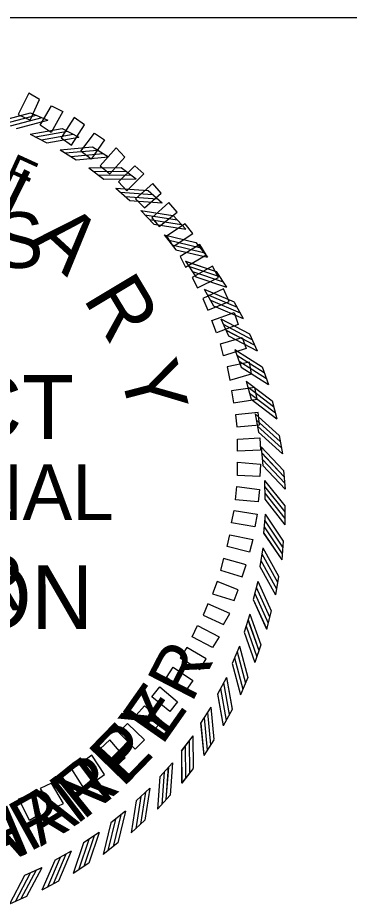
# Model space of a CAD drawing. Extents: x 16 to 1228740, y 11 to 152440.
# Drawn here: x 17.7977 to 17.8643, y 10.8205 to 10.9986 of the extents above; entities that cross this region are included whole.
import ezdxf

# ---------------------------------------------------------------- set-up
doc = ezdxf.new("R2010")
doc.units = 0
for name, color, linetype in [('R_No Plot', 7, 'Continuous'), ('STAMP_FRED', 7, 'Continuous'), ('STAMP_JUSTIN', 7, 'Continuous'), ('STAMP_PRELIM', 7, 'Continuous')]:
    doc.layers.add(name, color=color, linetype=linetype)

msp = doc.modelspace()

# ---------------------------------------------------------------- linework, layer by layer
at = {"layer": 'R_No Plot'}
msp.add_line((17.888, 10.99864), (17.47349, 10.99864), dxfattribs=at)
at = {"layer": 'STAMP_FRED'}
for p, q in [((17.80029, 10.97955), (17.80376, 10.97807)), ((17.80666, 10.9764), (17.80999, 10.97463)), ((17.80024, 10.97526), (17.80358, 10.97349)), ((17.80625, 10.97212), (17.80943, 10.97009)), ((17.81275, 10.97273), (17.81592, 10.9707)), ((17.81199, 10.9685), (17.81499, 10.96621)), ((17.81851, 10.96857), (17.82151, 10.96628)), ((17.8174, 10.96442), (17.82021, 10.96189)), ((17.82391, 10.96395), (17.82671, 10.96142)), ((17.82246, 10.95991), (17.82505, 10.95715)), ((17.82891, 10.9589), (17.83149, 10.95615)), ((17.82713, 10.95499), (17.82948, 10.95203)), ((17.83347, 10.95345), (17.83582, 10.9505)), ((17.83138, 10.9497), (17.83348, 10.94656)), ((17.83757, 10.94765), (17.83966, 10.94451)), ((17.83518, 10.94408), (17.83701, 10.94078)), ((17.84118, 10.94152), (17.843, 10.93822)), ((17.8385, 10.93817), (17.84005, 10.93472)), ((17.84427, 10.93512), (17.84581, 10.93169)), ((17.84132, 10.932), (17.84258, 10.92844)), ((17.84682, 10.92849), (17.84807, 10.92494)), ((17.84362, 10.92562), (17.84458, 10.92197)), ((17.84881, 10.92167), (17.84977, 10.91802)), ((17.84539, 10.91908), (17.84605, 10.91535)), ((17.85023, 10.91471), (17.85089, 10.91099)), ((17.84661, 10.9124), (17.84696, 10.90864)), ((17.85108, 10.90765), (17.85142, 10.9039)), ((17.84728, 10.90566), (17.84731, 10.90188)), ((17.84738, 10.89887), (17.8471, 10.89511)), ((17.85133, 10.90055), (17.85137, 10.89678)), ((17.84693, 10.89211), (17.84634, 10.88837)), ((17.851, 10.89345), (17.85073, 10.88969)), ((17.85009, 10.8864), (17.8495, 10.88268)), ((17.84591, 10.8854), (17.84502, 10.88173)), ((17.8486, 10.87945), (17.8477, 10.87579)), ((17.84435, 10.8788), (17.84316, 10.87522)), ((17.84225, 10.87235), (17.84076, 10.86888)), ((17.84653, 10.87265), (17.84534, 10.86908)), ((17.83962, 10.8661), (17.83786, 10.86276)), ((17.84392, 10.86605), (17.84243, 10.86258)), ((17.83649, 10.86009), (17.83445, 10.85691)), ((17.84076, 10.85968), (17.839, 10.85635)), ((17.83287, 10.85435), (17.83058, 10.85135)), ((17.83709, 10.85359), (17.83506, 10.85042)), ((17.82879, 10.84894), (17.82625, 10.84613)), ((17.83293, 10.84783), (17.83065, 10.84483)), ((17.82427, 10.84388), (17.82152, 10.84129)), ((17.82831, 10.84243), (17.82579, 10.83963)), ((17.81935, 10.83921), (17.81639, 10.83686)), ((17.82326, 10.83743), (17.82051, 10.83485)), ((17.81407, 10.83496), (17.81092, 10.83286)), ((17.81782, 10.83287), (17.81486, 10.83052)), ((17.80845, 10.83116), (17.80514, 10.82933)), ((17.80254, 10.82784), (17.79909, 10.82629)), ((17.81201, 10.82877), (17.80888, 10.82667)), ((17.80589, 10.82516), (17.80259, 10.82333)), ((17.79949, 10.82207), (17.79605, 10.82052))]:
    msp.add_line(p, q, dxfattribs=at)
for points in [[(17.79398, 10.97788), (17.80029, 10.97955)], [(17.79509, 10.9774), (17.8014, 10.97906)], [(17.79631, 10.97691), (17.80261, 10.97857)], [(17.79746, 10.9764), (17.80376, 10.97807)], [(17.80023, 10.97526), (17.80665, 10.9764)], [(17.8013, 10.97468), (17.80772, 10.97582)], [(17.80247, 10.97409), (17.80889, 10.97523)], [(17.80357, 10.97349), (17.81, 10.97463)], [(17.80625, 10.97212), (17.81274, 10.97273)], [(17.80726, 10.97146), (17.81376, 10.97206)], [(17.80838, 10.97078), (17.81487, 10.97138)], [(17.80943, 10.97009), (17.81593, 10.9707)], [(17.81198, 10.9685), (17.8185, 10.96857)], [(17.81294, 10.96776), (17.81946, 10.96782)], [(17.814, 10.96699), (17.82052, 10.96705)], [(17.81499, 10.96621), (17.82151, 10.96628)], [(17.8174, 10.96442), (17.8239, 10.96395)], [(17.81829, 10.9636), (17.8248, 10.96313)], [(17.81928, 10.96274), (17.82579, 10.96227)], [(17.8202, 10.96189), (17.82671, 10.96142)], [(17.82246, 10.95991), (17.8289, 10.9589)], [(17.82328, 10.95901), (17.82972, 10.95801)], [(17.8242, 10.95808), (17.83064, 10.95707)], [(17.82505, 10.95716), (17.83149, 10.95615)], [(17.82713, 10.95499), (17.83347, 10.95345)], [(17.82787, 10.95403), (17.83421, 10.9525)], [(17.82871, 10.95303), (17.83505, 10.95149)], [(17.82948, 10.95203), (17.83582, 10.9505)], [(17.83138, 10.9497), (17.83757, 10.94765)], [(17.83204, 10.94869), (17.83823, 10.94663)], [(17.83279, 10.94762), (17.83898, 10.94556)], [(17.83348, 10.94656), (17.83967, 10.94451)], [(17.83517, 10.94409), (17.84117, 10.94153)], [(17.83575, 10.94302), (17.84175, 10.94046)], [(17.83641, 10.94189), (17.84241, 10.93933)], [(17.83701, 10.94078), (17.84301, 10.93822)], [(17.83849, 10.93817), (17.84426, 10.93513)], [(17.83898, 10.93706), (17.84475, 10.93402)], [(17.83955, 10.93588), (17.84531, 10.93283)], [(17.84005, 10.93473), (17.84582, 10.93168)], [(17.84132, 10.93201), (17.84681, 10.92849)], [(17.84171, 10.93086), (17.84721, 10.92735)], [(17.84217, 10.92963), (17.84767, 10.92612)], [(17.84258, 10.92845), (17.84808, 10.92493)], [(17.84362, 10.92563), (17.84881, 10.92167)], [(17.84392, 10.92445), (17.8491, 10.9205)], [(17.84428, 10.92319), (17.84947, 10.91924)], [(17.84459, 10.92197), (17.84977, 10.91802)], [(17.84539, 10.91908), (17.85023, 10.91471)], [(17.84558, 10.91788), (17.85043, 10.91351)], [(17.84584, 10.9166), (17.85068, 10.91223)], [(17.84605, 10.91536), (17.85089, 10.91099)], [(17.84661, 10.91241), (17.85107, 10.90765)], [(17.84671, 10.9112), (17.85117, 10.90645)], [(17.84686, 10.9099), (17.85132, 10.90514)], [(17.84696, 10.90865), (17.85143, 10.90389)], [(17.84727, 10.90566), (17.85133, 10.90055)], [(17.84727, 10.90445), (17.85133, 10.89934)], [(17.84731, 10.90314), (17.85137, 10.89803)], [(17.84731, 10.90188), (17.85137, 10.89677)], [(17.84738, 10.89888), (17.851, 10.89345)], [(17.84728, 10.89767), (17.8509, 10.89225)], [(17.84721, 10.89636), (17.85083, 10.89094)], [(17.84711, 10.89511), (17.85073, 10.88969)], [(17.84692, 10.89211), (17.85009, 10.88641)], [(17.84672, 10.89092), (17.84989, 10.88521)], [(17.84634, 10.88838), (17.84951, 10.88267)], [(17.84655, 10.88962), (17.84971, 10.88391)], [(17.84591, 10.88541), (17.84859, 10.87946)], [(17.84533, 10.88295), (17.84801, 10.877)], [(17.84561, 10.88423), (17.8483, 10.87828)], [(17.84502, 10.88173), (17.84771, 10.87579)], [(17.84396, 10.87766), (17.84614, 10.87151)], [(17.84435, 10.87881), (17.84653, 10.87266)], [(17.84357, 10.87641), (17.84575, 10.87026)], [(17.84316, 10.87522), (17.84534, 10.86907)], [(17.84225, 10.87236), (17.84391, 10.86605)], [(17.84176, 10.87125), (17.84343, 10.86494)], [(17.84077, 10.86888), (17.84243, 10.86258)], [(17.84127, 10.87003), (17.84294, 10.86373)], [(17.83904, 10.86504), (17.84018, 10.85862)], [(17.83962, 10.86611), (17.84076, 10.85968)], [(17.83846, 10.86387), (17.8396, 10.85745)], [(17.83786, 10.86276), (17.839, 10.85634)], [(17.83649, 10.86009), (17.83709, 10.8536)], [(17.83514, 10.85796), (17.83575, 10.85146)], [(17.83582, 10.85908), (17.83643, 10.85258)], [(17.83446, 10.85691), (17.83506, 10.85041)], [(17.83287, 10.85436), (17.83293, 10.84784)], [(17.83212, 10.8534), (17.83219, 10.84688)], [(17.83058, 10.85135), (17.83065, 10.84483)], [(17.83135, 10.85234), (17.83142, 10.84582)], [(17.82797, 10.84805), (17.82749, 10.84154)], [(17.82879, 10.84894), (17.82831, 10.84244)], [(17.82626, 10.84613), (17.82579, 10.83963)], [(17.82711, 10.84706), (17.82664, 10.84055)], [(17.82427, 10.84388), (17.82326, 10.83744)], [(17.82244, 10.84214), (17.82144, 10.8357)], [(17.82338, 10.84306), (17.82237, 10.83661)], [(17.82152, 10.84129), (17.82051, 10.83485)], [(17.8184, 10.83847), (17.81686, 10.83213)], [(17.81936, 10.83921), (17.81782, 10.83287)], [(17.8164, 10.83686), (17.81486, 10.83052)], [(17.81739, 10.83763), (17.81585, 10.83129)], [(17.81407, 10.83496), (17.81202, 10.82877)], [(17.81198, 10.83355), (17.80993, 10.82736)], [(17.81305, 10.8343), (17.811, 10.82811)], [(17.81093, 10.83286), (17.80887, 10.82667)], [(17.80625, 10.82993), (17.80369, 10.82393)], [(17.80738, 10.83059), (17.80483, 10.82459)], [(17.80845, 10.83116), (17.80589, 10.82516)], [(17.80254, 10.82784), (17.79949, 10.82208)], [(17.80515, 10.82933), (17.80259, 10.82333)], [(17.79909, 10.82629), (17.79605, 10.82052)], [(17.80024, 10.82679), (17.7972, 10.82102)], [(17.80143, 10.82736), (17.79838, 10.82159)]]:
    msp.add_lwpolyline(points, dxfattribs=at)
at = {"layer": 'STAMP_JUSTIN'}
for p, q in [((17.80029, 10.97955), (17.80376, 10.97807)), ((17.80666, 10.9764), (17.80999, 10.97463)), ((17.80024, 10.97526), (17.80358, 10.97349)), ((17.80625, 10.97212), (17.80943, 10.97009)), ((17.81275, 10.97273), (17.81592, 10.97069)), ((17.81198, 10.9685), (17.81499, 10.96621)), ((17.81851, 10.96857), (17.8215, 10.96628)), ((17.8174, 10.96442), (17.8202, 10.96189)), ((17.82391, 10.96395), (17.8267, 10.96142)), ((17.82246, 10.95991), (17.82505, 10.95715)), ((17.82891, 10.9589), (17.83149, 10.95615)), ((17.82713, 10.95499), (17.82948, 10.95203)), ((17.83347, 10.95345), (17.83581, 10.9505)), ((17.83138, 10.9497), (17.83348, 10.94656)), ((17.83757, 10.94765), (17.83966, 10.94451)), ((17.83518, 10.94408), (17.83701, 10.94078)), ((17.84118, 10.94152), (17.843, 10.93822)), ((17.8385, 10.93817), (17.84005, 10.93472)), ((17.84427, 10.93512), (17.84581, 10.93169)), ((17.84132, 10.932), (17.84258, 10.92844)), ((17.84682, 10.92849), (17.84807, 10.92494)), ((17.84362, 10.92562), (17.84458, 10.92197)), ((17.84881, 10.92167), (17.84977, 10.91802)), ((17.84539, 10.91908), (17.84604, 10.91536)), ((17.85023, 10.91471), (17.85089, 10.91099)), ((17.84661, 10.91241), (17.84695, 10.90864)), ((17.85107, 10.90765), (17.85142, 10.9039)), ((17.84727, 10.90566), (17.84731, 10.90188)), ((17.84738, 10.89888), (17.8471, 10.89511)), ((17.85133, 10.90055), (17.85137, 10.89678)), ((17.84692, 10.89211), (17.84634, 10.88838)), ((17.851, 10.89345), (17.85073, 10.88969)), ((17.85009, 10.8864), (17.8495, 10.88268)), ((17.84591, 10.8854), (17.84502, 10.88173)), ((17.84859, 10.87946), (17.8477, 10.87579)), ((17.84435, 10.8788), (17.84316, 10.87522)), ((17.84225, 10.87236), (17.84076, 10.86888)), ((17.84653, 10.87265), (17.84534, 10.86908)), ((17.83962, 10.8661), (17.83785, 10.86276)), ((17.84391, 10.86605), (17.84243, 10.86258)), ((17.83649, 10.86009), (17.83445, 10.85691)), ((17.84076, 10.85968), (17.839, 10.85635)), ((17.83287, 10.85435), (17.83057, 10.85135)), ((17.83709, 10.85359), (17.83506, 10.85042)), ((17.82879, 10.84894), (17.82625, 10.84614)), ((17.83293, 10.84783), (17.83064, 10.84484)), ((17.82427, 10.84388), (17.82151, 10.84129)), ((17.82831, 10.84243), (17.82578, 10.83964)), ((17.81935, 10.83921), (17.81639, 10.83686)), ((17.82326, 10.83743), (17.82051, 10.83485)), ((17.81407, 10.83496), (17.81092, 10.83286)), ((17.81782, 10.83287), (17.81486, 10.83053)), ((17.80845, 10.83116), (17.80514, 10.82933)), ((17.80253, 10.82784), (17.79909, 10.82629)), ((17.81201, 10.82877), (17.80887, 10.82668)), ((17.80589, 10.82516), (17.80259, 10.82334)), ((17.79949, 10.82207), (17.79605, 10.82053))]:
    msp.add_line(p, q, dxfattribs=at)
for points in [[(17.79398, 10.97788), (17.80029, 10.97955)], [(17.79509, 10.9774), (17.8014, 10.97906)], [(17.7963, 10.97691), (17.80261, 10.97857)], [(17.79746, 10.9764), (17.80376, 10.97807)], [(17.80023, 10.97526), (17.80665, 10.9764)], [(17.8013, 10.97468), (17.80772, 10.97582)], [(17.80247, 10.97409), (17.80889, 10.97523)], [(17.80357, 10.97349), (17.81, 10.97463)], [(17.80624, 10.97212), (17.81274, 10.97273)], [(17.80726, 10.97146), (17.81376, 10.97206)], [(17.80838, 10.97078), (17.81487, 10.97138)], [(17.80943, 10.97009), (17.81593, 10.97069)], [(17.81198, 10.9685), (17.8185, 10.96857)], [(17.81294, 10.96776), (17.81946, 10.96782)], [(17.81399, 10.96699), (17.82052, 10.96705)], [(17.81499, 10.96621), (17.82151, 10.96628)], [(17.8174, 10.96442), (17.8239, 10.96395)], [(17.81829, 10.9636), (17.82479, 10.96313)], [(17.81928, 10.96274), (17.82578, 10.96227)], [(17.8202, 10.96189), (17.82671, 10.96142)], [(17.82246, 10.95991), (17.8289, 10.9589)], [(17.82328, 10.95901), (17.82972, 10.95801)], [(17.82419, 10.95808), (17.83064, 10.95707)], [(17.82504, 10.95715), (17.83149, 10.95615)], [(17.82713, 10.95499), (17.83347, 10.95345)], [(17.82787, 10.95403), (17.83421, 10.9525)], [(17.82871, 10.95302), (17.83505, 10.95149)], [(17.82948, 10.95203), (17.83582, 10.9505)], [(17.83137, 10.9497), (17.83757, 10.94765)], [(17.83204, 10.94869), (17.83823, 10.94663)], [(17.83279, 10.94762), (17.83898, 10.94556)], [(17.83348, 10.94656), (17.83967, 10.94451)], [(17.83517, 10.94409), (17.84117, 10.94153)], [(17.83575, 10.94302), (17.84175, 10.94046)], [(17.83641, 10.94189), (17.84241, 10.93933)], [(17.83701, 10.94078), (17.84301, 10.93822)], [(17.83849, 10.93817), (17.84426, 10.93513)], [(17.83898, 10.93706), (17.84475, 10.93402)], [(17.83954, 10.93588), (17.84531, 10.93283)], [(17.84005, 10.93473), (17.84582, 10.93168)], [(17.84131, 10.93201), (17.84681, 10.92849)], [(17.84171, 10.93086), (17.8472, 10.92735)], [(17.84217, 10.92963), (17.84767, 10.92612)], [(17.84258, 10.92845), (17.84808, 10.92493)], [(17.84362, 10.92563), (17.8488, 10.92167)], [(17.84391, 10.92445), (17.8491, 10.9205)], [(17.84427, 10.92319), (17.84946, 10.91924)], [(17.84458, 10.92197), (17.84977, 10.91802)], [(17.84538, 10.91908), (17.85023, 10.91471)], [(17.84558, 10.91788), (17.85043, 10.91351)], [(17.84584, 10.9166), (17.85068, 10.91223)], [(17.84605, 10.91536), (17.85089, 10.91099)], [(17.8466, 10.91241), (17.85107, 10.90766)], [(17.8467, 10.9112), (17.85117, 10.90645)], [(17.84685, 10.9099), (17.85132, 10.90515)], [(17.84696, 10.90865), (17.85142, 10.90389)], [(17.84727, 10.90566), (17.85133, 10.90055)], [(17.84727, 10.90445), (17.85133, 10.89934)], [(17.84731, 10.90314), (17.85137, 10.89803)], [(17.84731, 10.90188), (17.85137, 10.89678)], [(17.84738, 10.89888), (17.851, 10.89346)], [(17.84728, 10.89767), (17.8509, 10.89225)], [(17.84721, 10.89636), (17.85083, 10.89094)], [(17.8471, 10.89511), (17.85073, 10.88969)], [(17.84692, 10.89211), (17.85008, 10.88641)], [(17.84672, 10.89092), (17.84988, 10.88521)], [(17.84634, 10.88838), (17.8495, 10.88268)], [(17.84655, 10.88962), (17.84971, 10.88391)], [(17.84591, 10.88541), (17.84859, 10.87946)], [(17.84533, 10.88295), (17.84801, 10.87701)], [(17.84561, 10.88423), (17.84829, 10.87829)], [(17.84502, 10.88174), (17.8477, 10.87579)], [(17.84395, 10.87766), (17.84614, 10.87151)], [(17.84435, 10.87881), (17.84653, 10.87266)], [(17.84357, 10.87641), (17.84575, 10.87026)], [(17.84316, 10.87522), (17.84534, 10.86907)], [(17.84225, 10.87236), (17.84391, 10.86605)], [(17.84176, 10.87125), (17.84343, 10.86494)], [(17.84077, 10.86888), (17.84243, 10.86258)], [(17.84127, 10.87003), (17.84294, 10.86373)], [(17.83904, 10.86504), (17.84018, 10.85862)], [(17.83962, 10.86611), (17.84076, 10.85969)], [(17.83846, 10.86387), (17.8396, 10.85745)], [(17.83786, 10.86277), (17.839, 10.85634)], [(17.83649, 10.8601), (17.83709, 10.8536)], [(17.83514, 10.85796), (17.83575, 10.85147)], [(17.83582, 10.85908), (17.83643, 10.85258)], [(17.83445, 10.85691), (17.83506, 10.85041)], [(17.83287, 10.85436), (17.83293, 10.84784)], [(17.83212, 10.8534), (17.83219, 10.84688)], [(17.83058, 10.85135), (17.83064, 10.84483)], [(17.83135, 10.85234), (17.83142, 10.84582)], [(17.82796, 10.84805), (17.82749, 10.84155)], [(17.82879, 10.84894), (17.82831, 10.84244)], [(17.82626, 10.84614), (17.82578, 10.83963)], [(17.82711, 10.84706), (17.82663, 10.84055)], [(17.82427, 10.84388), (17.82326, 10.83744)], [(17.82244, 10.84215), (17.82144, 10.8357)], [(17.82338, 10.84306), (17.82237, 10.83662)], [(17.82152, 10.84129), (17.82051, 10.83485)], [(17.8184, 10.83847), (17.81686, 10.83213)], [(17.81935, 10.83921), (17.81782, 10.83287)], [(17.8164, 10.83686), (17.81486, 10.83052)], [(17.81739, 10.83763), (17.81585, 10.83129)], [(17.81407, 10.83496), (17.81201, 10.82877)], [(17.81198, 10.83355), (17.80992, 10.82736)], [(17.81305, 10.8343), (17.811, 10.82811)], [(17.81093, 10.83286), (17.80887, 10.82667)], [(17.80625, 10.82993), (17.80369, 10.82393)], [(17.80738, 10.83059), (17.80482, 10.82459)], [(17.80845, 10.83117), (17.80589, 10.82517)], [(17.80254, 10.82785), (17.79949, 10.82208)], [(17.80515, 10.82933), (17.80259, 10.82333)], [(17.79909, 10.82629), (17.79605, 10.82052)], [(17.80024, 10.8268), (17.7972, 10.82103)], [(17.80143, 10.82736), (17.79838, 10.82159)]]:
    msp.add_lwpolyline(points, dxfattribs=at)
at = {"layer": 'STAMP_PRELIM'}
for p, q in [((17.79996, 10.98347), (17.79783, 10.97916)), ((17.80208, 10.98222), (17.79996, 10.98347)), ((17.80021, 10.97803), (17.80208, 10.98222)), ((17.80221, 10.97703), (17.80453, 10.98091)), ((17.80453, 10.98091), (17.80678, 10.97978)), ((17.79783, 10.97916), (17.80021, 10.97803)), ((17.80678, 10.97978), (17.80446, 10.9756)), ((17.80903, 10.9786), (17.80646, 10.97453)), ((17.81115, 10.9771), (17.80903, 10.9786)), ((17.80446, 10.9756), (17.80221, 10.97703)), ((17.80853, 10.97303), (17.81115, 10.9771)), ((17.80646, 10.97453), (17.80853, 10.97303)), ((17.8104, 10.97185), (17.81315, 10.97541)), ((17.81515, 10.9741), (17.81246, 10.97022)), ((17.81315, 10.97541), (17.81515, 10.9741)), ((17.81746, 10.97247), (17.81428, 10.96885)), ((17.81921, 10.9706), (17.81746, 10.97247)), ((17.81246, 10.97022), (17.8104, 10.97185)), ((17.81621, 10.96728), (17.81921, 10.9706)), ((17.81428, 10.96885), (17.81621, 10.96728)), ((17.82121, 10.96891), (17.81796, 10.96566)), ((17.82303, 10.96728), (17.82121, 10.96891)), ((17.81965, 10.96385), (17.82303, 10.96728)), ((17.81796, 10.96566), (17.81965, 10.96385)), ((17.82483, 10.96535), (17.8214, 10.96222)), ((17.82653, 10.96341), (17.82483, 10.96535)), ((17.82315, 10.96041), (17.82653, 10.96341)), ((17.8214, 10.96222), (17.82315, 10.96041)), ((17.82808, 10.96153), (17.82465, 10.95841)), ((17.82971, 10.9596), (17.82808, 10.96153)), ((17.82615, 10.95666), (17.82971, 10.9596)), ((17.82465, 10.95841), (17.82615, 10.95666)), ((17.83133, 10.95722), (17.82758, 10.95478)), ((17.8329, 10.95528), (17.83133, 10.95722)), ((17.82758, 10.95478), (17.82896, 10.95266)), ((17.82896, 10.95266), (17.8329, 10.95528)), ((17.83428, 10.9531), (17.83033, 10.95066)), ((17.83558, 10.95103), (17.83428, 10.9531)), ((17.83033, 10.95066), (17.8314, 10.94853)), ((17.8314, 10.94853), (17.83558, 10.95103)), ((17.83683, 10.94872), (17.83278, 10.94647)), ((17.83803, 10.94647), (17.83683, 10.94872)), ((17.83278, 10.94647), (17.83383, 10.94435)), ((17.83383, 10.94435), (17.83803, 10.94647)), ((17.83903, 10.94416), (17.8349, 10.94222)), ((17.84021, 10.9416), (17.83903, 10.94416)), ((17.8349, 10.94222), (17.8359, 10.93985)), ((17.8359, 10.93985), (17.84021, 10.9416)), ((17.83671, 10.93778), (17.84115, 10.93941)), ((17.84115, 10.93941), (17.84196, 10.93697)), ((17.83765, 10.93535), (17.83671, 10.93778)), ((17.84196, 10.93697), (17.83765, 10.93535)), ((17.83846, 10.9331), (17.84278, 10.93441)), ((17.83903, 10.93072), (17.83846, 10.9331)), ((17.84278, 10.93441), (17.84358, 10.93216)), ((17.84358, 10.93216), (17.83903, 10.93072)), ((17.84428, 10.92941), (17.83978, 10.92847)), ((17.84465, 10.9271), (17.84428, 10.92941)), ((17.83978, 10.92847), (17.84028, 10.92585)), ((17.84028, 10.92585), (17.84465, 10.9271)), ((17.84533, 10.92435), (17.84065, 10.92366)), ((17.84578, 10.92203), (17.84533, 10.92435)), ((17.84065, 10.92366), (17.84103, 10.92128)), ((17.84103, 10.92128), (17.84578, 10.92203)), ((17.84603, 10.91935), (17.84146, 10.91885)), ((17.84146, 10.91885), (17.84171, 10.91641)), ((17.84628, 10.91685), (17.84603, 10.91935)), ((17.84171, 10.91641), (17.84628, 10.91685)), ((17.84183, 10.91397), (17.84633, 10.91422)), ((17.84183, 10.91153), (17.84183, 10.91397)), ((17.84633, 10.91422), (17.84646, 10.91178)), ((17.84646, 10.91178), (17.84183, 10.91153)), ((17.84183, 10.90935), (17.84646, 10.90891)), ((17.84183, 10.90666), (17.84183, 10.90935)), ((17.84646, 10.90891), (17.84633, 10.90647)), ((17.84633, 10.90647), (17.84183, 10.90666)), ((17.84146, 10.90178), (17.84171, 10.90447)), ((17.84171, 10.90447), (17.84628, 10.90385)), ((17.84628, 10.90385), (17.84603, 10.90135)), ((17.84603, 10.90135), (17.84146, 10.90178)), ((17.84065, 10.89716), (17.84115, 10.8996)), ((17.84115, 10.8996), (17.84578, 10.89891)), ((17.84578, 10.89891), (17.84533, 10.89635)), ((17.84533, 10.89635), (17.84065, 10.89716)), ((17.83978, 10.89241), (17.84033, 10.89472)), ((17.84033, 10.89472), (17.84496, 10.89378)), ((17.84496, 10.89378), (17.84428, 10.89128)), ((17.84428, 10.89128), (17.83978, 10.89241)), ((17.83903, 10.88997), (17.83846, 10.88766)), ((17.84358, 10.88872), (17.83903, 10.88997)), ((17.84278, 10.88628), (17.84358, 10.88872)), ((17.83846, 10.88766), (17.84278, 10.88628)), ((17.83778, 10.88535), (17.83683, 10.88291)), ((17.84196, 10.88372), (17.83778, 10.88535)), ((17.83683, 10.88291), (17.84115, 10.88153)), ((17.84115, 10.88153), (17.84196, 10.88372)), ((17.8359, 10.88091), (17.83496, 10.8786)), ((17.84028, 10.87897), (17.8359, 10.88091)), ((17.83496, 10.8786), (17.83903, 10.87672)), ((17.83903, 10.87672), (17.84028, 10.87897)), ((17.83278, 10.87422), (17.83383, 10.87653)), ((17.83383, 10.87653), (17.83815, 10.87422)), ((17.83683, 10.8721), (17.83278, 10.87422)), ((17.83815, 10.87422), (17.83683, 10.8721)), ((17.83165, 10.8721), (17.83033, 10.87003)), ((17.83558, 10.86985), (17.83165, 10.8721)), ((17.83033, 10.87003), (17.83428, 10.86772)), ((17.83428, 10.86772), (17.83558, 10.86985)), ((17.82758, 10.8661), (17.82896, 10.86816)), ((17.82896, 10.86816), (17.8329, 10.86547)), ((17.83133, 10.86328), (17.82758, 10.8661)), ((17.8329, 10.86547), (17.83133, 10.86328)), ((17.82465, 10.86222), (17.82628, 10.86422)), ((17.82628, 10.86422), (17.82978, 10.86122)), ((17.82828, 10.85928), (17.82465, 10.86222)), ((17.82321, 10.86041), (17.82153, 10.85853)), ((17.82665, 10.85728), (17.82321, 10.86041)), ((17.82978, 10.86122), (17.82828, 10.85928)), ((17.82153, 10.85853), (17.8249, 10.85535)), ((17.81978, 10.85685), (17.81803, 10.85503)), ((17.82315, 10.85353), (17.81978, 10.85685)), ((17.8249, 10.85535), (17.82665, 10.85728)), ((17.81803, 10.85503), (17.82128, 10.85166)), ((17.81621, 10.85353), (17.81428, 10.85178)), ((17.81933, 10.84997), (17.81621, 10.85353)), ((17.82128, 10.85166), (17.82315, 10.85353)), ((17.81428, 10.85178), (17.81753, 10.84835)), ((17.81258, 10.85047), (17.81053, 10.84891)), ((17.81515, 10.8466), (17.81258, 10.85047)), ((17.81753, 10.84835), (17.81933, 10.84997)), ((17.80858, 10.84766), (17.80646, 10.84622)), ((17.81115, 10.84366), (17.80858, 10.84766)), ((17.81053, 10.84891), (17.81328, 10.84528)), ((17.80646, 10.84622), (17.80908, 10.84235)), ((17.81328, 10.84528), (17.81515, 10.8466)), ((17.80453, 10.84485), (17.80221, 10.84378)), ((17.80221, 10.84378), (17.80465, 10.83972)), ((17.8069, 10.84078), (17.80453, 10.84485)), ((17.80908, 10.84235), (17.81115, 10.84366)), ((17.79796, 10.84172), (17.80028, 10.84266)), ((17.80028, 10.84266), (17.80221, 10.8386)), ((17.80008, 10.83735), (17.79796, 10.84172)), ((17.80465, 10.83972), (17.8069, 10.84078)), ((17.80221, 10.8386), (17.80008, 10.83735))]:
    msp.add_line(p, q, dxfattribs=at)

# ---------------------------------------------------------------- texts
at = {"layer": 'STAMP_FRED'}
for s, height, rotation, p in [('F', 0.00686, 335.3628, (17.79425, 10.96525)), ('R', 0.01042, 62.6418, (17.83263, 10.86077)), ('E', 0.01042, 54.981, (17.82667, 10.85221)), ('P', 0.01042, 46.9554, (17.81927, 10.84417)), ('R', 0.01042, 38.9298, (17.81081, 10.83725)), ('A', 0.01042, 31.6338, (17.80236, 10.83204)), ('H', 0.01042, 22.8786, (17.79144, 10.82727))]:
    msp.add_text(s, height=height, rotation=rotation, dxfattribs=at).set_placement(p)
for s, height, p in [('ARKANSAS', 0.011194, (17.72135, 10.94837)), ('PROFESSIONAL', 0.0111938, (17.70056, 10.89771)), ('ENGINEER', 0.011194, (17.72082, 10.87959))]:
    msp.add_text(s, height=height, dxfattribs=at).set_placement(p)
at = {"layer": 'STAMP_JUSTIN'}
for s, height, rotation, p in [('F', 0.00686, 335.3628, (17.79425, 10.96525)), ('Y', 0.01042, 53.4433, (17.82593, 10.85139)), ('E', 0.01042, 45.7825, (17.81878, 10.8438)), ('N', 0.01042, 37.0272, (17.80946, 10.83639)), ('R', 0.01042, 29.0016, (17.80002, 10.83092)), ('A', 0.01042, 21.7056, (17.79084, 10.82713))]:
    msp.add_text(s, height=height, rotation=rotation, dxfattribs=at).set_placement(p)
for s, height, p in [('ARKANSAS', 0.011194, (17.72135, 10.94837)), ('PROFESSIONAL', 0.0111936, (17.70056, 10.89771)), ('ENGINEER', 0.011194, (17.72082, 10.87959))]:
    msp.add_text(s, height=height, dxfattribs=at).set_placement(p)
at = {"layer": 'STAMP_PRELIM'}
for s, rotation, p in [('N', 333.841, (17.7859, 10.96147)), ('A', 317.4238, (17.7999, 10.95353)), ('R', 301.0067, (17.81071, 10.94228)), ('Y', 284.5896, (17.81803, 10.92797))]:
    msp.add_text(s, height=0.01184, rotation=rotation, dxfattribs=at).set_placement(p)
for s, p in [('SUBJECT', (17.73109, 10.91403)), ('REVISION', (17.73109, 10.87585))]:
    msp.add_text(s, height=0.012794, dxfattribs=at).set_placement(p)

doc.saveas('drawing.dxf')
